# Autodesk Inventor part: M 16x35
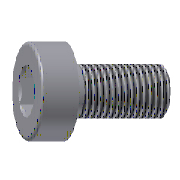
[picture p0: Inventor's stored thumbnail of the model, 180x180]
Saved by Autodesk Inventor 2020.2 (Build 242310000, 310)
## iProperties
Manager: www.cadconsulting.pl
Company: Fabian Stasiak CAD Consulting
Created: 2014-02
Part Number: M 16x35
Material: Stal, miękka
Description: Socket Head Cap Screw DIN 912 - 12.9
Document SubType Name: Modeling
Designer: F.Stasiak
Standard Revision: 1
Manufacturer: DME
Language: pl-PL
Size Designation: 16x35
Categories: <MemberInstance><Categories><Category DisplayName="Forma wtryskowa" InternalName="349578f2-f4d4-4954-8c09-8e99297a61c0" Mnemonic="MOLD"><Category DisplayName="C
Mass: 0.133121 g
Surface Area: 2.01441 cm^2
Volume: 0.133121 cm^3
Density: 7.85 g/cm^3
Appearance: Częściowo polerowana
Catalog Web Link: www.expertbooks.pl
IsCustomPart: 0
Author: F.Stasiak
Subject: Zbiór ćwiczeń. Autodesk Inventor 2020. Kurs Professional
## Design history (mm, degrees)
sketch "Sketch1"
  geometry: L1 (0, -45.2)-(0, 26.2) reference; L2 (8.083, 16)-(12, 16); L3 (12, 16)-(12, 0); L4 (12, 0)-(8, 0); L5 (8, 0)-(8, -35); L6 (8, -35)-(0, -35); L7 (0, 3.794)-(0, -35); L8 (0, 3.794)-(7, 8); L9 (7, 8)-(7, 14.917); L10 (7, 14.917)-(8.083, 16); 1 further point
  constraints: 18 end point, 4 vertical, 3 horizontal, 2 point on line
  dimensions: "d0" = 24 diameter of L3 L1 (= dk); "d1" = 16 distance between parallel lines of L4 L2 (= k); "d2" = 16 diameter of L5 L1 (= d); "d3" = 35 distance between parallel lines of L6 L4 (= L); "d4" = 59 deg angle of L1 L8; "d5" = 45 deg angle of L1 L10; "d6" = 14 diameter of L9 L1 (= sw); "d7" = 16.16581 diameter of L2.start L1 (= 1.1547 x sw); "d8" = 8 distance from line of L8.end L2 (= t)
revolve "Revolution1" sketch "Sketch1" stored, may be unused: angle "d44" = 90 deg
sketch "Sketch2"
  geometry: L1 (0, 8.083)-(7, 4.041); L2 (7, 4.041)-(7, -4.041); L3 (7, -4.041)-(0, -8.083); L4 (0, -8.083)-(-7, -4.041); L5 (-7, -4.041)-(-7, 4.041); L6 (-7, 4.041)-(0, 8.083); 3 further points
  constraints: 12 end point, 2 vertical alignment, 1 coincident, 14 other
extrude "Extrusion1" cut sketch "Sketch2" taper "d9" = 0 deg; stored distance "d45" = 10
thread "Thread1" dims "d10" = 35 (= b), "d11" = 0
chamfer "Chamfer1" distance "d12" = 1 (= 0.5 x P); stored, may be unused: second distance "d50" = 2, angle "d51" = 45 deg
fillet "Fillet1" dims "d13" = 1 (= 0.5 x P)
body "Solid1"
other parameters: "d" = 16 [user parameter; used in 1 equation term], "L" = 35 [user parameter; used in 1 equation term], "dk" = 24 [user parameter; used in 1 equation term], "b" = 35 [user parameter; used in 1 equation term], "k" = 16 [user parameter; used in 1 equation term], "sw" = 14 [user parameter; used in 2 equation terms], "t" = 8 [user parameter; used in 1 equation term], "P" = 2 [user parameter; used in 2 equation terms], "d14" = 0, "d15" = 0, "d55" = 0
